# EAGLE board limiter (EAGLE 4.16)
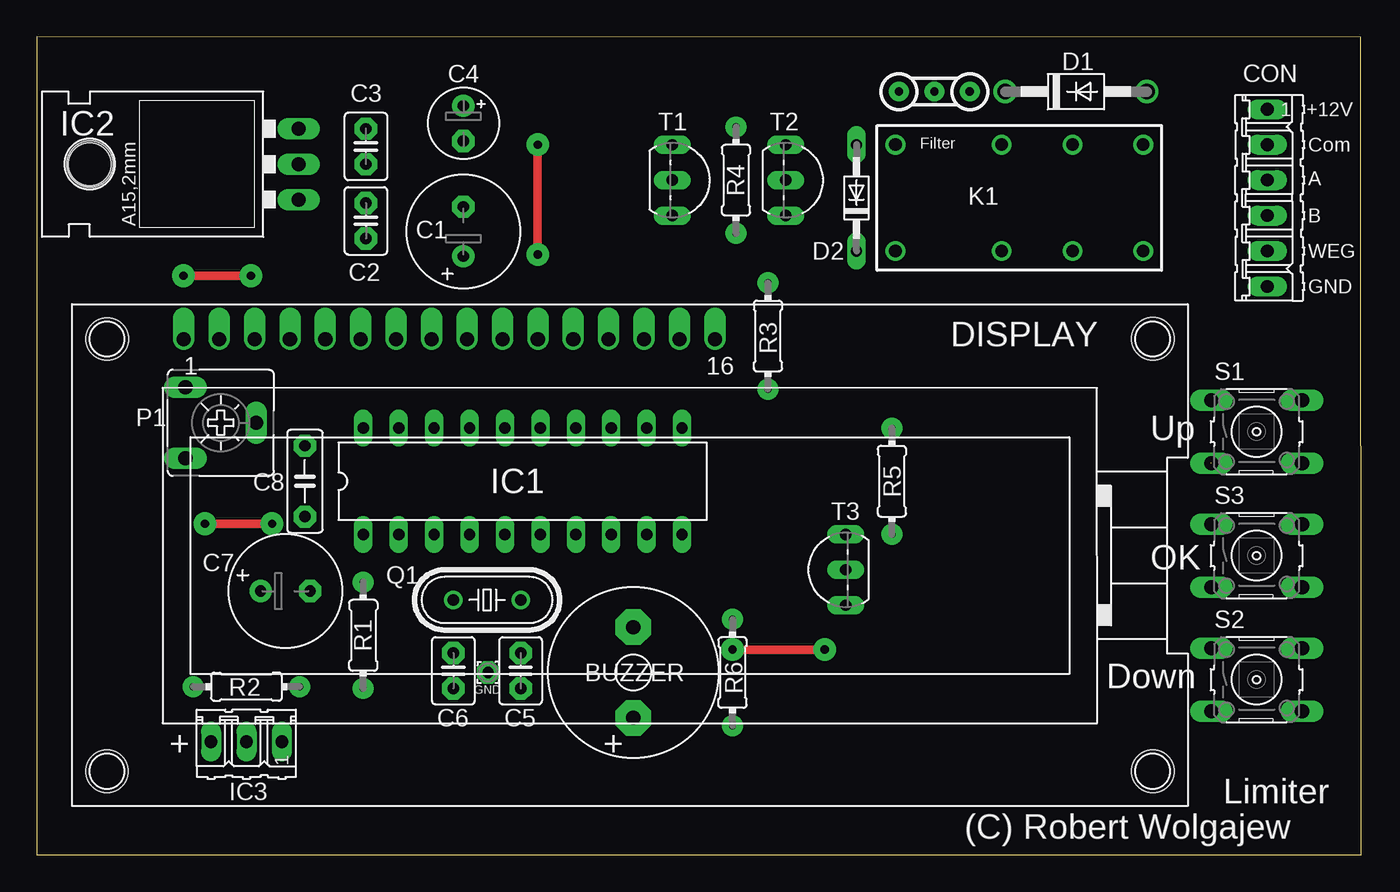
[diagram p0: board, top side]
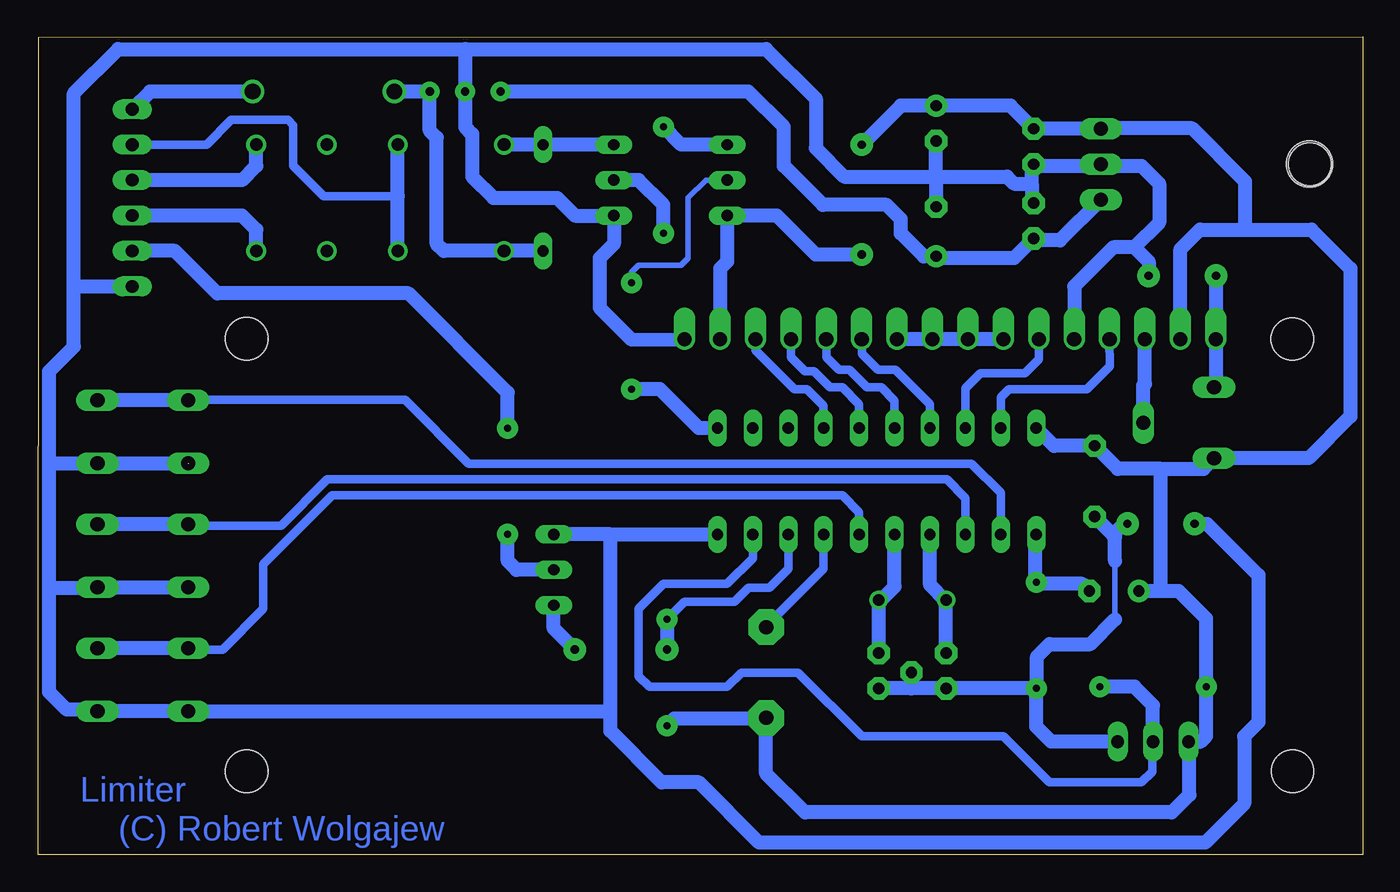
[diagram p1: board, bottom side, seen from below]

Size 95.03 x 58.66 mm. Coordinates in mm from the lower left corner, seen from the top.
Outline: 0,0 95.03,0 94.99,58.64 0,58.66 0,0
Copper layers (1*16): Top 0.035mm / dielectric 1.5mm / Bottom 0.035mm
Design rules "default": minimum track width 24mil, minimum drill 15mil, track to track 30mil, track to pad 30mil, pad to pad 30mil, via to via 30mil, smd to smd 30mil, copper to edge 20mil, drill to drill 10mil, minimum pad ring 10mil, minimum via ring 20mil, stop-mask expansion 4mil, vias tented up to drill 0mil, thermal gap 10mil
Net classes: 1 1mm: width 1 mm, drill 1 mm; 2 2mm: width 2 mm, drill 2 mm
Holes 3.05 mm at 5.06,36.99 5.05,6 80.06,37 80.07,6 3.82,49.52

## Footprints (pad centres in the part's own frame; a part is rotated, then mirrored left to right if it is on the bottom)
AL60P = drill 1.016 pad 2.54 octagon: 1 -3.251,0; 2 3.251,0
E3,5-8 = drill 0.813 pad 1.6 round: + -1.778,0 | drill 0.813 pad 1.6 octagon: - 1.778,0
C2.5-3 = drill 0.813 pad 1.6 octagon: 1 -1.27,0; 2 1.27,0
E2,5-5 = drill 0.813 pad 1.6 round: + -1.27,0 | drill 0.813 pad 1.6 octagon: - 1.27,0
C5B2.5 = drill 0.813 pad 1.6 octagon: 1 -2.54,0; 2 2.54,0
06P = drill 0.914 long: 1 -6.35,0; 2 -3.81,0; 3 -1.27,0; 4 1.27,0; 5 3.81,0; 6 6.35,0
DO41-10 = drill 1.118 round: A 5.08,0; C -5.08,0
DO34-7 = drill 0.813 long: A 3.81,0; C -3.81,0
ARTTRONIC1602 = drill 1.016 offset: 1 0.008,0.016; 2 2.548,0.016; 3 5.088,0.016; 4 7.628,0.016; 5 10.168,0.016; 6 12.708,0.016; 7 15.248,0.016; 8 17.788,0.016; 9 20.328,0.016; 10 22.868,0.016; 11 25.408,0.016; 12 27.948,0.016; 13 30.488,0.016; 14 33.028,0.016; 15 35.568,0.016; 16 38.108,0.016
FILTRDSS = drill 0.6 pad 1.422 round: GND -8.89,5.08; IN -11.43,5.08; OUT -6.35,5.08
1,6/0,8 = drill 0.813 pad 1.6 octagon: 1 0,0
DIL20 = drill 0.813 long: 1 -11.43,-3.81; 2 -8.89,-3.81; 3 -6.35,-3.81; 4 -3.81,-3.81; 5 -1.27,-3.81; 6 1.27,-3.81; 7 3.81,-3.81; 8 6.35,-3.81; 9 8.89,-3.81; 10 11.43,-3.81; 11 11.43,3.81; 12 8.89,3.81; 13 6.35,3.81; 14 3.81,3.81; 15 1.27,3.81; 16 -1.27,3.81; 17 -3.81,3.81; 18 -6.35,3.81; 19 -8.89,3.81; 20 -11.43,3.81
78XXL = drill 1.016 long: GND 0,-3.81; IN -2.54,-3.81; OUT 2.54,-3.81 | hole 3.302: 0,11.176
03P = drill 0.914 long: 1 -2.54,0; 2 0,0; 3 2.54,0
DS-BT = drill 0.9 round: 1 -8.89,-3.81; 4 -1.27,-3.81; 6 3.81,-3.81; 8 8.89,-3.81; 9 8.89,3.81; 11 3.81,3.81; 13 -1.27,3.81; 16 -8.89,3.81
CA6V = drill 1.016 long: A -2.54,-2.54; E 2.54,-2.54; S 0,2.54
HC49/S = drill 0.813 round: 1 -2.413,0; 2 2.413,0
0204/7 = drill 0.5 pad 1.499 round: 1 -3.81,0; 2 3.81,0
B3F-10XX = drill 1.016 long: 1 -3.251,2.261; 2 3.251,2.261; 3 -3.251,-2.261; 4 3.251,-2.261
TO92-EBC = drill 0.813 long: B 0,-1.27; C -2.54,-1.27; E 2.54,-1.27

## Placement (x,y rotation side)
BUZZER  AL60P  [AL60P]  42.81,13.08 90 top
C1  220uF  [E3,5-8]  30.62,44.7 90 top
C2  100nF  [C2.5-3]  23.63,45.46 90 top
C3  100nF  [C2.5-3]  23.63,50.8 270 top
C4  100uF  [E2,5-5]  30.62,52.45 270 top
C5  33pF  [C2.5-3]  34.73,13.2 90 top
C6  33pF  [C2.5-3]  29.9,13.2 90 top
C7  10uF  [E3,5-8]  17.85,18.92 0 top
C8  100nF  [C5B2.5]  19.25,26.79 270 top
CON  [06P]  88.27,47.11 270 top
D1  1N4004  [DO41-10]  74.56,54.73 0 top
D2  BAT85  [DO34-7]  58.81,47.11 90 top
DISPLAY  162E  [ARTTRONIC1602]  10.55,36.95 0 top
FILTER  FILTRDSS  [FILTRDSS]  55.51,59.81 180 top
GND  [1,6/0,8]  32.39,13.08 0 top
IC1  AT89C4051P  [DIL20]  34.87,26.79 0 top
IC2  7805  [78XXL]  15,49.52 90 top
IC3  DS1820  [03P]  15.06,8.12 180 top
K1  JRC-27F/012S  [DS-BT]  70.49,47.11 0 top
P1  10K  [CA6V]  13.22,30.98 270 top
Q1  [HC49/S]  32.31,18.28 0 top
R1  10K  [0204/7]  23.44,15.74 90 top
R2  4K7  [0204/7]  15.06,12.06 180 top
R3  2.2K  [0204/7]  52.46,37.21 270 top
R4  2.2K  [0204/7]  50.17,48.38 90 top
R5  10K  [0204/7]  61.35,26.79 270 top
R6  4K7  [0204/7]  49.92,13.08 90 top
S1  [B3F-10XX]  87.51,30.35 0 top
S2  [B3F-10XX]  87.51,12.57 0 top
S3  [B3F-10XX]  87.51,21.46 0 top
T1  BC560  [TO92-EBC]  46.87,48.38 270 top
T2  BC548  [TO92-EBC]  55,48.38 270 top
T3  BC548  [TO92-EBC]  56.78,20.44 90 top

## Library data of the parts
BUZZER = buzzer
C1 C4 C7 R1-R6 = rcl
C2 C3 C5 C6 C8 = capacitor-wima
CON IC3 = con-amp-quick
D1 D2 = diode
DISPLAY = displaytech_(chr)
FILTER = filtrDSS
GND = wirepad
IC1 = atmel
IC2 = v-reg
K1 = relay
P1 = pot
Q1 = crystal
S1-S3 = switch-omron
T1 = transistor-pnp
T2 T3 = transistor-npn

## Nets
N$1: C1.- C2.2 C3.2 C4.- C5.1 C6.1 C8.2 CON.6 DISPLAY.1 DISPLAY.5 DISPLAY.16 FILTER.GND GND.1 IC1.10 IC2.GND IC3.1 P1.A R1.1 S1.3 S1.4 S2.3 S2.4 S3.3 S3.4 T2.E T3.E
N$2: DISPLAY.4 IC1.19
N$3: DISPLAY.6 IC1.18
N$4: C1.+ C2.1 FILTER.OUT IC2.IN
N$5 [1mm]: DISPLAY.11 IC1.17
N$6: C5.2 IC1.5 Q1.2
N$7: C6.2 IC1.4 Q1.1
N$8: DISPLAY.12 IC1.16
N$9: C7.- IC1.1 R1.2
N$10: DISPLAY.13 IC1.15
N$11: DISPLAY.14 IC1.14
N$12: DISPLAY.7 DISPLAY.8 DISPLAY.9 DISPLAY.10
N$13: DISPLAY.3 P1.S
N$14: R4.1 T2.B
N$15: R4.2 T1.C
N$16: IC1.11 R3.2
N$17: D2.A K1.16 T2.C
N$18: D1.C D2.C FILTER.IN K1.1
N$19: CON.1 D1.A
N$20: CON.2 K1.4 K1.13
N$21: CON.3 K1.9
N$22: CON.4 K1.8
N$23: R3.1 T1.B
N$24: IC1.2 S1.1 S1.2
N$27: BUZZER.1 C3.1 C4.+ C7.+ C8.1 DISPLAY.2 DISPLAY.15 IC1.20 IC2.OUT IC3.3 P1.E R2.2 R6.1 T1.E
N$28: IC1.9 IC3.2 R2.1
N$29: BUZZER.2 IC1.7
N$30: IC1.8 R6.2 T3.C
N$31: R5.2 T3.B
N$32: IC1.6 S2.1 S2.2
N$33: IC1.3 S3.1 S3.2
N$34: CON.5 R5.1

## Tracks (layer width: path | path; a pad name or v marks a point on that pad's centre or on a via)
N$1  (via drill 0.6)  (1 unrouted)
  Top 0.61: v15.38,41.52 v10.55,41.52 | v16.9,23.74 v12.07,23.74
  Bottom 0.406: 17.79,16.89 17.79,21.08
  Bottom 1.016: S1.3 S1.4 94.22,28.09 94.24,28.06 | 84.23,28.09 84.21,28.06 | 84.23,19.2 S3.3 | 84.23,19.2 S3.4 90.79,19.2 90.81,19.17 94.24,19.17 | 84.23,19.2 84.21,19.17 | 18.93,49.4 23.5,49.4 C3.2 23.76,49.4 23.76,48.13 | C2.2 23.76,46.86 23.76,48.13 | 30.62,48.64 C1.- | 30.62,48.64 C4.- | 30.62,48.64 25.54,48.64 25.03,48.13 23.76,48.13 | C6.1 29.98,11.93 | 23.5,11.93 C6.1 | C6.1 32.39,11.93 | 32.39,11.93 C5.1 | 17.54,8.12 IC3.1 22.36,8.12 23.44,9.2 R1.1 23.5,11.93 | 17.95,22.95 17.79,22.79 17.79,21.08 | 17.95,22.95 C8.2 | 17.79,16.89 19.57,15.11 22.49,15.11 23.38,14.22 23.38,12.06 23.5,11.93 | DISPLAY.5 20.71,40.76 17.92,43.56 16.39,43.56 | 16.39,43.56 14.61,45.33 14.61,48.13 15.88,49.4 18.93,49.4 | 18.93,49.4 IC2.GND | v10.55,41.52 DISPLAY.1 10.55,33.65 P1.A | v15.38,41.52 15.38,42.54 16.39,43.56 | 30.62,48.64 37.22,48.64 39.25,50.67 39.25,54.22 42.81,57.78 64.4,57.78 | DISPLAY.16 52.46,36.95 54.75,39.24 54.75,42.79 53.73,43.81 T2.E 56.52,45.84 57.79,47.11 62.37,47.11 63.89,48.64 63.89,51.68 64.4,52.19 FILTER.GND 64.4,57.78 | S2.4 S2.3 84.23,10.31 84.21,10.28 53.98,10.28 | 90.81,10.28 90.79,10.31 S2.4 | 53.98,22.98 IC1.10 | 53.98,22.98 T3.E | v12.07,23.74 11.19,23.74 7.5,20.06 7.5,9.52 8.52,8.5 8.52,3.68 11.31,0.88 43.32,0.88 47.63,5.2 50.3,5.2 53.98,8.89 53.98,10.28 | 17.95,22.95 | 17.95,22.95 17.41,23.49 17.15,23.49 v16.9,23.74 | 53.98,10.28 53.98,22.98 | 64.4,57.78 89.29,57.78 92.47,54.6 92.47,40.76 | 92.47,40.76 92.47,36.44 94.24,34.67 94.24,28.06 | 94.24,19.17 94.24,11.68 92.97,10.41 90.81,10.41 90.76,10.36 S2.4 | 94.24,19.17 94.24,28.06 | 92.47,40.76 CON.6 | 32.39,11.93 GND.1
N$2
  Bottom 0.61: IC1.19 25.98,32.83 25.41,33.4 19.82,33.4 18.17,35.05 DISPLAY.4
N$3
  Bottom 0.61: IC1.18 28.52,33.46 27.44,34.54 24.27,34.54 23.25,35.56 DISPLAY.6
N$4
  Bottom 1.016: IC2.IN 21.73,44.06 23.5,44.06 C2.1 25.03,42.79 30.62,42.79 C1.+ 31.5,42.92 33.16,44.57 33.16,45.59 34.17,46.6 38.74,46.6 41.54,49.4 41.54,52.19 44.08,54.73 FILTER.OUT
N$5
  Bottom 0.61: IC1.17 31.06,32.32 33.54,34.79 34.81,34.79 35.95,35.94 DISPLAY.11
N$6
  Bottom 1.016: IC1.5 33.6,19.24 34.68,18.16 34.73,18.2 Q1.2 34.73,14.65 34.68,14.6 34.73,14.55 C5.2
N$7
  Bottom 1.016: 29.9,18.2 29.85,18.16 | 29.9,18.2 Q1.1 29.9,14.65 29.85,14.6 29.9,14.55 C6.2 | IC1.4 31.06,19.36 29.9,18.2
N$8
  Bottom 0.61: IC1.16 33.6,32.57 34.55,33.52 35.57,33.52 36.84,34.79 37.6,34.79 38.49,35.68 DISPLAY.12
N$9
  Bottom 1.016: R1.2 23.5,19.68 | IC1.1 23.5,22.92 23.5,19.68 | 23.5,19.68 23.5,19.62 R1.2 | R1.2 23.5,19.49 23.5,19.43 20.14,19.43 C7.-
N$10
  Bottom 0.61: IC1.15 36.14,32.32 37.35,33.52 38.24,33.52 39.38,34.67 40.01,34.67 41.03,35.68 DISPLAY.13
N$11
  Bottom 0.61: IC1.14 38.68,32.19 39.89,33.4 40.78,33.4 43.57,36.19 DISPLAY.14
N$12
  Bottom 1.016: DISPLAY.7 DISPLAY.8 DISPLAY.9 DISPLAY.10
N$13
  Bottom 1.016: P1.S 15.76,33.65 15.63,33.78 DISPLAY.3
N$14
  Bottom 1.016: R4.1 50.17,46.6 51.95,48.38 T2.B
N$15
  Bottom 1.016: T1.C 48.9,50.92 R4.2
N$16
  Bottom 1.016: IC1.11 47.63,30.6 50.43,33.4 R3.2
N$17
  Bottom 1.016: K1.16 D2.A T2.C 53.48,50.92
N$18
  Bottom 1.016: D1.C FILTER.IN 66.94,51.94 66.43,51.43 66.43,43.81 65.92,43.3 K1.1 D2.C
N$19
  Bottom 1.016: D1.A 87,54.73 CON.1
N$20
  Bottom 0.61: CON.2 82.94,50.92 81.16,52.7 77.1,52.7 76.72,52.32 76.72,49.4 74.56,47.24 69.22,47.24
  Bottom 1.016: K1.4 69.22,47.24 K1.13
N$21
  Bottom 1.016: K1.9 79.38,49.4 80.4,48.38 CON.3
N$22
  Bottom 1.016: K1.8 79.38,44.83 80.4,45.84 CON.4
N$23
  Bottom 0.406: T1.B 47.13,48.38 48.4,47.11 48.4,42.79 48.9,42.29 51.95,42.29 52.46,41.78 R3.1
N$24
  Bottom 0.406: 84.21,32.63 84.23,32.61 S1.1
  Bottom 0.61: IC1.2 25.98,25.97 28.08,28.06 64.14,28.06 68.72,32.63 84.34,32.63 84.31,32.61 S1.1
  Bottom 1.016: 90.79,32.61 S1.2 | S1.1 90.79,32.61 | 90.79,32.61 90.81,32.63
N$27  (via drill 0.6)
  Top 0.61: v35.95,50.92 v35.95,43.05
  Bottom 1.016: C3.1 IC2.OUT 18.78,52.09 12.25,52.09 8.44,48.28 8.44,44.83 | C3.1 23.76,52.19 | C3.1 25.28,53.72 C4.+ 33.16,53.72 v35.95,50.92 | IC1.20 22.17,29.33 C8.1 17.6,27.68 14.49,27.68 | 14.49,27.68 11.44,27.68 P1.E 3.9,28.44 0.9,31.44 0.9,42.03 3.69,44.83 8.44,44.83 | 14.49,18.92 C7.+ | 14.49,18.92 13.22,18.92 11.25,16.95 R2.2 11.25,8.52 11.64,8.12 12.46,8.12 | 14.49,18.92 14.49,27.68 | DISPLAY.2 13.09,43.43 11.69,44.83 8.44,44.83 | R6.1 49.41,9.77 42.81,9.77 BUZZER.1 42.81,5.84 40.01,3.04 13.73,3.04 12.46,4.31 12.46,8.12 | v35.95,43.05 39.25,43.05 42.05,45.84 T1.E 45.6,42.54 46.11,42.03 DISPLAY.15 | 12.46,8.12 IC3.3
N$28
  Bottom 0.61: IC1.9 43.76,21.27 45.6,19.43 50.17,19.43 51.95,17.65 51.95,12.82 51.19,12.06 45.6,12.06 44.59,13.08 40.52,13.08 35.95,8.5 25.79,8.5 22.49,5.2 15.88,5.2 15.12,5.96 15.12,8 15.06,8.06 IC3.2
  Bottom 1.016: IC3.2 15.06,10.73 16.39,12.06 R2.1
N$29
  Bottom 0.61: BUZZER.2 42.81,16.38 38.68,20.51 IC1.7
N$30  (via drill 0.6)
  Top 0.61: v49.92,14.73 v56.52,14.73
  Bottom 0.61: IC1.8 41.22,20.51 42.55,19.17 44.08,19.17 45.09,18.16 48.65,18.16 R6.2
  Bottom 1.016: T3.C 58.05,16.25 v56.52,14.73 | R6.2 v49.92,14.73
N$31
  Bottom 1.016: T3.B 60.72,20.44 61.35,21.08 R5.2
N$32
  Bottom 0.61: IC1.6 36.14,24.57 37.35,25.78 73.92,25.78 78.88,20.82 78.88,17.65 81.8,14.73 84.21,14.73 84.26,14.78 S2.1
  Bottom 1.016: 90.79,14.83 S2.2 | S2.1 90.79,14.83 | 90.79,14.83 90.81,14.85
N$33
  Bottom 0.61: IC1.3 28.52,25.58 29.85,26.92 74.3,26.92 77.61,23.62 84.21,23.62 84.26,23.67 S3.1
  Bottom 1.016: S3.1 84.31,23.72 84.34,23.74 84.36,23.72 S3.2
N$34
  Bottom 1.016: R5.1 61.35,33.14 68.46,40.25 82.18,40.25 85.23,43.3 CON.5

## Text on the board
Bottom: Limiter | (C) Robert Wolgajew
tNames: +12V | Com | A | B | WEG | GND | Up | OK | Down | + | + | Limiter | (C) Robert Wolgajew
